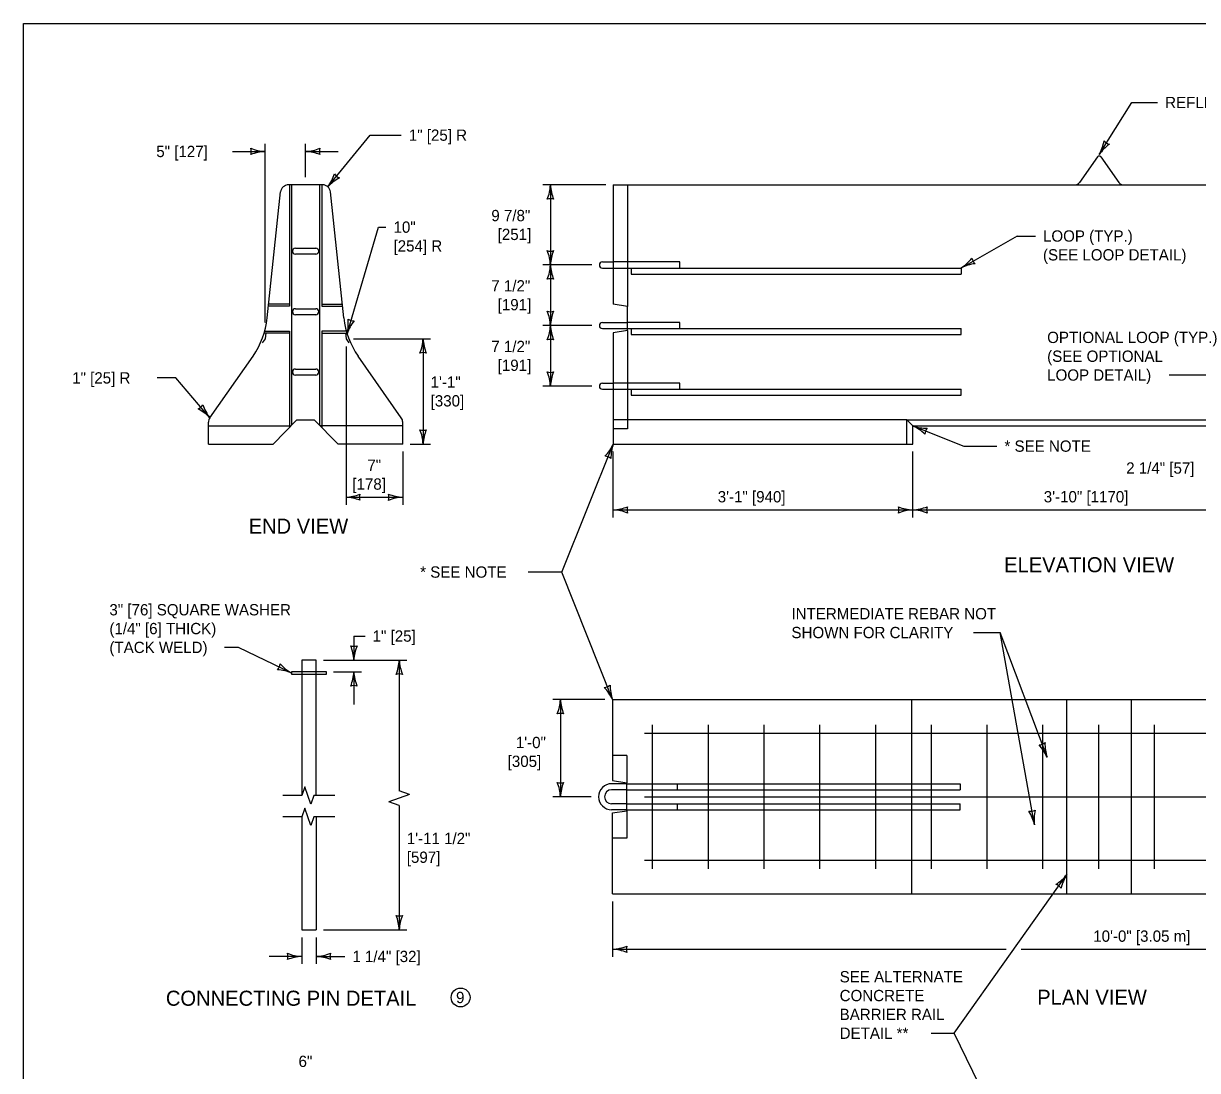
# Model space of a CAD drawing. Extents: x 49991.4 to 50021, y 49987.6 to 50011.4.
# Drawn here: x 49999.38 to 50005.62, y 49993.44 to 49999 of the extents above; entities that cross this region are included whole.
import ezdxf

# ---------------------------------------------------------------- set-up
doc = ezdxf.new("R2010")
doc.units = 0
for name, color, linetype in [('Level 1', 7, 'Continuous'), ('Level 2', 7, 'Continuous'), ('Level 3', 7, 'Continuous'), ('Level 4', 7, 'Continuous'), ('Level 6', 7, 'Continuous')]:
    doc.layers.add(name, color=color, linetype=linetype)

msp = doc.modelspace()

# ---------------------------------------------------------------- linework, layer by layer
at = {"layer": 'Level 1'}
for p, q in [((50000.6793, 49997.435), (50000.75, 49998.1041)), ((50000.9736, 49998.142), (50000.7921, 49998.142)), ((50000.7966, 49998.142), (50000.7966, 49997.4968)), ((50000.8081, 49998.142), (50000.8081, 49996.865)), ((50000.957, 49998.142), (50000.957, 49996.865)), ((50000.9685, 49998.142), (50000.9685, 49997.4968)), ((50001.0858, 49997.435), (50001.0151, 49998.1041)), ((50002.518, 49998.1414), (50007.607, 49998.1414)), ((50002.518, 49998.1414), (50002.518, 49997.5077)), ((50000.829, 49997.8057), (50000.9364, 49997.8057)), ((50000.9364, 49997.7735), (50000.829, 49997.7735)), ((50002.4602, 49997.7324), (50002.518, 49997.7323)), ((50002.4602, 49997.7002), (50002.518, 49997.7002)), ((50000.7966, 49997.4968), (50000.6858, 49997.4968)), ((50000.7966, 49997.5074), (50000.6869, 49997.5074)), ((50000.829, 49997.484), (50000.9364, 49997.484)), ((50000.9685, 49997.5074), (50001.0782, 49997.5074)), ((50000.9685, 49997.4968), (50001.0793, 49997.4968)), ((50002.5934, 49997.4961), (50002.518, 49997.5077)), ((50002.5934, 49997.3675), (50002.5934, 49997.4961)), ((50000.9364, 49997.4518), (50000.829, 49997.4518)), ((50002.4602, 49997.4107), (50002.5934, 49997.4106)), ((50000.7966, 49997.3541), (50000.6628, 49997.3541)), ((50000.6661, 49997.3654), (50000.7966, 49997.3654)), ((50000.7966, 49997.3654), (50000.7966, 49996.8533)), ((50000.9685, 49997.3654), (50000.9685, 49996.8533)), ((50001.099, 49997.3654), (50000.9685, 49997.3654)), ((50000.9685, 49997.3541), (50001.1023, 49997.3541)), ((50002.4602, 49997.3785), (50002.5934, 49997.3784)), ((50002.5934, 49997.3675), (50002.518, 49997.356)), ((50002.518, 49997.356), (50002.518, 49996.7646)), ((50000.3738, 49996.9047), (50000.6035, 49997.2325)), ((50001.3913, 49996.9047), (50001.1616, 49997.2325)), ((50000.829, 49997.1635), (50000.9364, 49997.1635)), ((50000.9364, 49997.1313), (50000.829, 49997.1313)), ((50002.4602, 49997.0884), (50002.518, 49997.0883)), ((50002.4602, 49997.0562), (50002.518, 49997.0562)), ((50000.3661, 49996.7651), (50000.3661, 49996.8804)), ((50000.7098, 49996.7651), (50000.8365, 49996.8938)), ((50000.8365, 49996.8938), (50000.9286, 49996.8938)), ((50001.0553, 49996.7651), (50000.9286, 49996.8938)), ((50001.399, 49996.7651), (50001.399, 49996.8804)), ((50004.0777, 49996.8932), (50006.1232, 49996.8932)), ((50004.0777, 49996.7646), (50004.0777, 49996.8932)), ((50004.0777, 49996.8932), (50004.1097, 49996.8611)), ((50004.1097, 49996.8611), (50006.0912, 49996.8611)), ((50004.1097, 49996.7646), (50004.1097, 49996.8611)), ((50000.3661, 49996.7651), (50000.7098, 49996.7651)), ((50001.399, 49996.7651), (50001.0553, 49996.7651)), ((50002.518, 49996.7646), (50004.1097, 49996.7646)), ((50000.9386, 49995.6169), (50000.8624, 49995.6169)), ((50000.8624, 49995.6169), (50000.8624, 49994.8978)), ((50000.9386, 49994.8977), (50000.9386, 49995.6169)), ((50000.8092, 49995.5561), (50000.992, 49995.5561)), ((50000.8092, 49995.5407), (50000.8092, 49995.5561)), ((50000.992, 49995.5407), (50000.8092, 49995.5407)), ((50000.992, 49995.5561), (50000.992, 49995.5407)), ((50002.5138, 49995.4076), (50007.6787, 49995.4076)), ((50002.5138, 49995.4076), (50002.5138, 49994.9771)), ((50004.9281, 49994.3747), (50004.9281, 49995.4076)), ((50005.2728, 49994.3747), (50005.2728, 49995.4076)), ((50002.6839, 49995.2287), (50007.5087, 49995.2287)), ((50002.7255, 49995.2739), (50002.7255, 49994.5084)), ((50003.0219, 49995.2739), (50003.0219, 49994.5084)), ((50003.3182, 49995.2739), (50003.3182, 49994.5084)), ((50003.6145, 49995.2739), (50003.6145, 49994.5084)), ((50003.9109, 49995.2739), (50003.9109, 49994.5084)), ((50004.2072, 49995.2739), (50004.2072, 49994.5084)), ((50004.5036, 49995.2739), (50004.5036, 49994.5084)), ((50004.7999, 49995.2739), (50004.7999, 49994.5084)), ((50005.0963, 49995.2739), (50005.0963, 49994.5084)), ((50005.3926, 49995.2739), (50005.3926, 49994.5084)), ((50002.5138, 49994.9771), (50002.5892, 49994.9656)), ((50002.5892, 49994.9604), (50002.5093, 49994.9604)), ((50002.5892, 49994.9284), (50002.5093, 49994.9284)), ((50002.5892, 49994.8168), (50002.5892, 49994.9656)), ((50002.5892, 49994.8537), (50002.5093, 49994.8537)), ((50002.6839, 49994.8911), (50007.5087, 49994.8911)), ((50002.5892, 49994.8217), (50002.5093, 49994.8217)), ((50002.5138, 49994.805), (50002.5892, 49994.8168)), ((50002.5138, 49994.3747), (50002.5138, 49994.805)), ((50000.8624, 49994.7844), (50000.8624, 49994.1841)), ((50000.9386, 49994.7843), (50000.9386, 49994.1841)), ((50002.6839, 49994.5537), (50007.5087, 49994.5537)), ((50002.5138, 49994.3747), (50007.6787, 49994.3747)), ((50000.8624, 49994.1841), (50000.9386, 49994.1841))]:
    msp.add_line(p, q, dxfattribs=at)
msp.add_lwpolyline([(49999.3835, 49998.9992), (50016.7501, 49998.9992), (50016.7501, 49987.7988), (49999.3835, 49987.7988)], close=True, dxfattribs=at)
for centre, radius, start, end in [((50000.7921, 49998.0996), 0.0423, 90, 173.97247), ((50000.973, 49998.0996), 0.0423, 6.02753, 90), ((50000.829, 49997.7896), 0.0161, 90, 270), ((50000.9364, 49997.7896), 0.0161, 270, 90), ((50002.4602, 49997.7163), 0.0161, 90, 270), ((50000.829, 49997.4679), 0.0161, 90, 270), ((50000.9364, 49997.4679), 0.0161, 270, 90), ((50000.2498, 49997.4803), 0.4318, 324.97771, 353.97247), ((50001.5153, 49997.4803), 0.4318, 186.02753, 215.02229), ((50002.4602, 49997.3946), 0.0161, 90, 270), ((50000.829, 49997.1474), 0.0161, 90, 270), ((50000.9364, 49997.1474), 0.0161, 270, 90), ((50002.4602, 49997.0723), 0.0161, 90, 270), ((50000.4084, 49996.8804), 0.0423, 144.97771, 180), ((50001.3567, 49996.8804), 0.0423, 0, 35.02229), ((50002.5093, 49994.8911), 0.0693, 90, 270), ((50002.5093, 49994.8911), 0.0374, 90, 270)]:
    msp.add_arc(centre, radius, start, end, dxfattribs=at)
at = {"layer": 'Level 2'}
msp.add_circle((50001.7068, 49993.8249), 0.05, dxfattribs=at)
at = {"layer": 'Level 3'}
for p, q in [((50005.1004, 49998.3024), (50005.2734, 49998.5794)), ((50005.2734, 49998.5794), (50005.411, 49998.5794)), ((50001.0015, 49998.1309), (50001.2252, 49998.406)), ((50001.2252, 49998.406), (50001.3915, 49998.406)), ((50000.6676, 49997.411), (50000.6676, 49998.3594)), ((50000.8828, 49998.182), (50000.8828, 49998.3594)), ((50000.4942, 49998.3194), (50000.6676, 49998.3194)), ((50000.8828, 49998.3194), (50001.0563, 49998.3194)), ((50005.0923, 49998.2909), (50004.9952, 49998.154)), ((50005.1086, 49998.2909), (50005.2057, 49998.154)), ((50002.478, 49998.1414), (50002.144, 49998.1414)), ((50002.184, 49998.1414), (50002.184, 49997.7163)), ((50001.1032, 49997.3512), (50001.2701, 49997.9175)), ((50001.2701, 49997.9175), (50001.3101, 49997.9175)), ((50004.6654, 49997.8702), (50004.3662, 49997.7002)), ((50004.6654, 49997.8702), (50004.7618, 49997.8702)), ((50002.4041, 49997.7163), (50002.144, 49997.7163)), ((50002.184, 49997.7163), (50002.184, 49997.3946)), ((50000.6708, 49997.3554), (50000.6675, 49997.3239)), ((50001.0943, 49997.3554), (50001.0976, 49997.3239)), ((50002.4041, 49997.3946), (50002.144, 49997.3946)), ((50002.184, 49997.3946), (50002.184, 49997.0723)), ((50000.6675, 49997.3239), (50000.6528, 49997.303)), ((50001.0976, 49997.3239), (50001.1123, 49997.303)), ((50001.0976, 49997.2839), (50001.0976, 49996.4423)), ((50001.1376, 49997.3239), (50001.5474, 49997.3239)), ((50001.5074, 49997.3239), (50001.5074, 49996.7651)), ((50000.1932, 49997.1164), (50000.0934, 49997.1164)), ((50000.3738, 49996.9047), (50000.1932, 49997.1164)), ((50005.7745, 49997.1316), (50005.4716, 49997.1316)), ((50002.4041, 49997.0723), (50002.144, 49997.0723)), ((50004.1097, 49996.8611), (50004.3802, 49996.7538)), ((50001.3992, 49996.7251), (50001.3992, 49996.4423)), ((50001.439, 49996.7651), (50001.5474, 49996.7651)), ((50002.2448, 49996.0849), (50002.518, 49996.7646)), ((50002.518, 49996.375), (50002.518, 49996.7246)), ((50004.1097, 49996.375), (50004.1097, 49996.7246)), ((50004.3802, 49996.7538), (50004.557, 49996.7538)), ((50001.0976, 49996.4823), (50001.3992, 49996.4823)), ((50002.518, 49996.415), (50004.1097, 49996.415)), ((50004.1097, 49996.415), (50006.0912, 49996.415)), ((50002.2448, 49996.0849), (50002.065, 49996.0849)), ((50002.5138, 49995.4076), (50002.2448, 49996.0849)), ((50001.1392, 49995.7449), (50001.1392, 49995.6171)), ((50001.1392, 49995.7449), (50001.1992, 49995.7449)), ((50004.4327, 49995.7636), (50004.5745, 49995.7636)), ((50004.8236, 49995.1014), (50004.5745, 49995.7636)), ((50004.7566, 49994.7424), (50004.5745, 49995.7636)), ((50000.5268, 49995.6847), (50000.4514, 49995.6847)), ((50000.8092, 49995.5483), (50000.5268, 49995.6847)), ((50000.9786, 49995.6171), (50001.4205, 49995.6171)), ((50001.3806, 49995.6171), (50001.3806, 49994.9226)), ((50001.032, 49995.5552), (50001.1792, 49995.5552)), ((50001.1392, 49995.5552), (50001.1392, 49995.3818)), ((50002.4738, 49995.4077), (50002.1971, 49995.4077)), ((50002.2371, 49995.4077), (50002.2371, 49994.8913)), ((50001.4352, 49994.9032), (50001.3806, 49994.9226)), ((50001.3806, 49994.8838), (50001.3256, 49994.8644)), ((50001.3806, 49994.845), (50001.3256, 49994.8644)), ((50001.4352, 49994.9032), (50001.3806, 49994.8838)), ((50002.4, 49994.8913), (50002.1971, 49994.8913)), ((50001.3806, 49994.845), (50001.3806, 49994.1843)), ((50004.3296, 49993.635), (50004.9281, 49994.4779)), ((50002.5138, 49994.3347), (50002.5138, 49994.0407)), ((50000.9786, 49994.1843), (50001.4205, 49994.1843)), ((50000.8624, 49994.1441), (50000.8624, 49994.0028)), ((50000.9386, 49994.1441), (50000.9386, 49994.0028)), ((50000.8624, 49994.0428), (50000.689, 49994.0428)), ((50000.9386, 49994.0428), (50001.0915, 49994.0428)), ((50002.5138, 49994.0807), (50004.6061, 49994.0807)), ((50004.6861, 49994.0807), (50007.6787, 49994.0807)), ((50004.2077, 49993.635), (50004.3296, 49993.635)), ((50005.0362, 49992.19), (50004.3296, 49993.635))]:
    msp.add_line(p, q, dxfattribs=at)
for centre, radius, start, end in [((50004.897, 49998.4159), 0.233, 330.85037, 350.10022), ((50005.284, 49998.177), 0.2223, 125.47907, 145.66258), ((50005.1683, 49998.4111), 0.0548, 220.16188, 255.88424), ((50000.5394, 49998.3194), 0.0548, 342.13882, 17.86118), ((50000.6791, 49998.5521), 0.233, 247.92284, 267.17269), ((50000.6768, 49998.0972), 0.2223, 92.36048, 112.54399), ((50000.8713, 49998.5521), 0.233, 272.82731, 292.07716), ((50000.8737, 49998.0972), 0.2223, 67.45601, 87.63952), ((50001.011, 49998.3194), 0.0548, 162.13882, 197.86118), ((50005.1004, 49998.2851), 0.01, 35.34894, 144.65106), ((50000.8137, 49998.2688), 0.233, 323.70951, 342.95936), ((50001.1681, 49997.9837), 0.2223, 118.33821, 138.52171), ((50001.0824, 49998.2304), 0.0548, 213.02101, 248.74337), ((50001.9619, 49998.1505), 0.2223, 337.45601, 357.63952), ((50002.4167, 49998.1529), 0.233, 182.82731, 202.07716), ((50004.9708, 49998.1714), 0.03, 270, 324.65106), ((50005.2301, 49998.1714), 0.03, 215.34894, 270), ((50002.184, 49998.0132), 0.0548, 72.13882, 107.86118), ((50002.184, 49997.8445), 0.0548, 252.13882, 287.86118), ((50001.9513, 49997.7048), 0.233, 2.82731, 22.07716), ((50002.4061, 49997.7072), 0.2223, 157.45601, 177.63952), ((50004.2485, 49997.8888), 0.2223, 301.96607, 322.14958), ((50004.4712, 49997.4922), 0.233, 97.52843, 116.77828), ((50004.4777, 49997.7635), 0.0548, 191.74441, 227.46677), ((50001.9619, 49997.7255), 0.2223, 337.45601, 357.63952), ((50002.4167, 49997.7278), 0.233, 182.82731, 202.07716), ((50002.184, 49997.5881), 0.0548, 72.13882, 107.86118), ((50002.184, 49997.5228), 0.0548, 252.13882, 287.86118), ((50001.9513, 49997.3831), 0.233, 2.82731, 22.07716), ((50002.4061, 49997.3854), 0.2223, 157.45601, 177.63952), ((50000.8767, 49997.406), 0.233, 346.40859, 5.65844), ((50001.3137, 49997.2796), 0.2223, 141.03729, 161.2208), ((50001.1394, 49997.4742), 0.0548, 235.7201, 271.44246), ((50001.9619, 49997.4037), 0.2223, 337.45601, 357.63952), ((50002.4167, 49997.4061), 0.233, 182.82731, 202.07716), ((50001.2852, 49997.3331), 0.2223, 337.45601, 357.63952), ((50001.7401, 49997.3354), 0.233, 182.82731, 202.07716), ((50002.184, 49997.2664), 0.0548, 72.13882, 107.86118), ((50001.5074, 49997.1957), 0.0548, 72.13882, 107.86118), ((50002.184, 49997.2005), 0.0548, 252.13882, 287.86118), ((50001.9513, 49997.0608), 0.233, 2.82731, 22.07716), ((50002.4061, 49997.0631), 0.2223, 157.45601, 177.63952), ((50000.2906, 49997.0022), 0.0548, 292.59303, 328.31539), ((50000.5487, 49997.0418), 0.2223, 197.91022, 218.09373), ((50000.2041, 49996.7449), 0.233, 43.28152, 62.53137), ((50004.0193, 49996.6579), 0.2223, 45.83501, 66.01852), ((50004.1848, 49997.0816), 0.233, 251.20631, 270.45616), ((50004.2289, 49996.8138), 0.0548, 140.51782, 176.24018), ((50001.5074, 49996.8933), 0.0548, 252.13882, 287.86118), ((50001.2746, 49996.7536), 0.233, 2.82731, 22.07716), ((50001.7295, 49996.7559), 0.2223, 157.45601, 177.63952), ((50002.3153, 49996.8559), 0.2223, 315.56008, 335.74359), ((50002.7382, 49996.6885), 0.233, 160.93138, 180.18123), ((50002.4702, 49996.6456), 0.0548, 50.24289, 85.96525), ((50001.0866, 49996.7051), 0.2231, 272.82731, 292.07716), ((50001.0888, 49996.2697), 0.2129, 67.45601, 87.63952), ((50001.2204, 49996.4823), 0.0524, 162.13882, 197.86118), ((50001.4084, 49996.7045), 0.2223, 247.45601, 267.63952), ((50001.271, 49996.4823), 0.0548, 342.13882, 17.86118), ((50001.4107, 49996.2496), 0.233, 92.82731, 112.07716), ((50002.5065, 49996.6477), 0.233, 272.82731, 292.07716), ((50002.5088, 49996.1929), 0.2223, 67.45601, 87.63952), ((50002.6462, 49996.415), 0.0548, 162.13882, 197.86118), ((50004.1189, 49996.6371), 0.2223, 247.45601, 267.63952), ((50003.9815, 49996.415), 0.0548, 342.13882, 17.86118), ((50004.1212, 49996.1823), 0.233, 92.82731, 112.07716), ((50004.0982, 49996.6477), 0.233, 272.82731, 292.07716), ((50004.1005, 49996.1929), 0.2223, 67.45601, 87.63952), ((50004.2379, 49996.415), 0.0548, 162.13882, 197.86118), ((50001.1392, 49995.7453), 0.0548, 252.13882, 287.86118), ((50000.9065, 49995.6056), 0.233, 2.82731, 22.07716), ((50001.3614, 49995.608), 0.2223, 157.45601, 177.63952), ((50000.6937, 49995.604), 0.0548, 316.3746, 352.09696), ((50000.914, 49995.7444), 0.2223, 221.69179, 241.8753), ((50001.1584, 49995.6263), 0.2223, 337.45601, 357.63952), ((50001.6133, 49995.6286), 0.233, 182.82731, 202.07716), ((50000.7184, 49995.3337), 0.233, 67.06309, 86.31294), ((50000.9171, 49995.5643), 0.2223, 337.45601, 357.63952), ((50001.3719, 49995.5667), 0.233, 182.82731, 202.07716), ((50001.3806, 49995.4889), 0.0548, 72.13882, 107.86118), ((50001.1392, 49995.427), 0.0548, 72.13882, 107.86118), ((50002.4665, 49995.5268), 0.0548, 273.80036, 309.52272), ((50002.3018, 49995.311), 0.233, 24.48885, 43.7387), ((50002.7236, 49995.4811), 0.2223, 179.11755, 199.30106), ((50002.015, 49995.4168), 0.2223, 337.45601, 357.63952), ((50002.4698, 49995.4192), 0.233, 182.82731, 202.07716), ((50002.2371, 49995.2795), 0.0548, 72.13882, 107.86118), ((50004.7784, 49995.2214), 0.0548, 272.74951, 308.47187), ((50004.6098, 49995.0087), 0.233, 23.438, 42.68785), ((50005.0347, 49995.171), 0.2223, 178.0667, 198.25021), ((50002.2371, 49995.0195), 0.0548, 252.13882, 287.86118), ((50002.0044, 49994.8798), 0.233, 2.82731, 22.07716), ((50002.4592, 49994.8822), 0.2223, 157.45601, 177.63952), ((50004.7341, 49994.8686), 0.0548, 262.24768, 297.97004), ((50004.5295, 49994.6902), 0.233, 12.93618, 32.18603), ((50004.9769, 49994.7723), 0.2223, 167.56488, 187.74838), ((50004.7523, 49994.6139), 0.2223, 302.07943, 322.26294), ((50005.1245, 49994.3525), 0.233, 147.45073, 166.70058), ((50004.8539, 49994.3733), 0.0548, 36.76224, 72.4846), ((50001.3806, 49994.3125), 0.0548, 252.13882, 287.86118), ((50001.1479, 49994.1728), 0.233, 2.82731, 22.07716), ((50001.6027, 49994.1752), 0.2223, 157.45601, 177.63952), ((50000.8715, 49994.265), 0.2223, 247.45601, 267.63952), ((50000.7342, 49994.0428), 0.0548, 342.13882, 17.86118), ((50000.8739, 49993.8101), 0.233, 92.82731, 112.07716), ((50000.9271, 49994.2756), 0.233, 272.82731, 292.07716), ((50000.9294, 49993.8207), 0.2223, 67.45601, 87.63952), ((50001.0668, 49994.0428), 0.0548, 162.13882, 197.86118), ((50002.5023, 49994.3134), 0.233, 272.82731, 292.07716), ((50002.5047, 49993.8585), 0.2223, 67.45601, 87.63952), ((50002.642, 49994.0807), 0.0548, 162.13882, 197.86118)]:
    msp.add_arc(centre, radius, start, end, dxfattribs=at)
at = {"layer": 'Level 4'}
for p, q in [((50002.5934, 49998.1414), (50002.5934, 49997.4961)), ((50002.871, 49997.7323), (50002.518, 49997.7323)), ((50002.871, 49997.7002), (50002.871, 49997.7323)), ((50002.518, 49997.7002), (50004.3662, 49997.7002)), ((50002.6136, 49997.7002), (50002.6136, 49997.6681)), ((50002.6136, 49997.6681), (50004.3662, 49997.6681)), ((50004.3662, 49997.7002), (50004.3662, 49997.6681)), ((50002.871, 49997.4106), (50002.5934, 49997.4106)), ((50002.871, 49997.3784), (50002.871, 49997.4106)), ((50002.5934, 49997.3784), (50004.3662, 49997.3784)), ((50002.5934, 49997.3675), (50002.5934, 49996.845)), ((50002.6136, 49997.3784), (50002.6136, 49997.3461)), ((50002.6136, 49997.3461), (50004.3662, 49997.3461)), ((50004.3662, 49997.3461), (50004.3662, 49997.3784)), ((50002.871, 49997.0883), (50002.518, 49997.0883)), ((50002.518, 49997.0562), (50004.3662, 49997.0562)), ((50002.6136, 49997.0562), (50002.6136, 49997.0238)), ((50002.871, 49997.0562), (50002.871, 49997.0883)), ((50004.3662, 49997.0238), (50004.3662, 49997.0562)), ((50002.6136, 49997.0238), (50004.3662, 49997.0238)), ((50000.3661, 49996.8616), (50000.8048, 49996.8616)), ((50001.399, 49996.8616), (50000.9603, 49996.8616)), ((50004.0777, 49996.8932), (50002.518, 49996.8932)), ((50002.5934, 49996.845), (50002.518, 49996.845)), ((50004.1055, 49994.3747), (50004.1055, 49995.4076)), ((50002.5892, 49995.1103), (50002.5138, 49995.1103)), ((50002.5892, 49995.1103), (50002.5892, 49994.9656)), ((50002.5892, 49994.9604), (50004.362, 49994.9604)), ((50002.5892, 49994.9284), (50004.362, 49994.9284)), ((50002.86, 49994.9284), (50002.86, 49994.9604)), ((50004.362, 49994.9604), (50004.362, 49994.9284)), ((50002.5892, 49994.8537), (50004.362, 49994.8537)), ((50002.86, 49994.8217), (50002.86, 49994.8537)), ((50004.362, 49994.8217), (50004.362, 49994.8537)), ((50002.5892, 49994.8217), (50004.362, 49994.8217)), ((50002.5892, 49994.8168), (50002.5892, 49994.6718)), ((50002.5892, 49994.6718), (50002.5138, 49994.6718))]:
    msp.add_line(p, q, dxfattribs=at)
at = {"layer": 'Level 6'}
for p, q in [((50000.8786, 49994.9435), (50000.8624, 49994.8977)), ((50000.8948, 49994.8977), (50000.8786, 49994.9435)), ((50000.8624, 49994.8977), (50000.7624, 49994.8979)), ((50000.911, 49994.8521), (50000.8948, 49994.8977)), ((50000.9272, 49994.8977), (50000.911, 49994.8521)), ((50001.0386, 49994.8975), (50000.9272, 49994.8977)), ((50000.8786, 49994.8301), (50000.8624, 49994.7843)), ((50000.8948, 49994.7843), (50000.8786, 49994.8301)), ((50000.8624, 49994.7843), (50000.7624, 49994.7845)), ((50000.911, 49994.7387), (50000.8948, 49994.7843)), ((50000.9272, 49994.7843), (50000.911, 49994.7387)), ((50001.0386, 49994.7841), (50000.9272, 49994.7843))]:
    msp.add_line(p, q, dxfattribs=at)

# ---------------------------------------------------------------- texts
at = {"layer": 'Level 2'}
for s, height, p in [('REFLECTOR  6', 0.06, (50005.451, 49998.5495)), ('1" [25] R', 0.06, (50001.4315, 49998.376)), ('5" [127]', 0.06, (50000.0892, 49998.2894)), ('9 7/8"', 0.06, (50001.8699, 49997.9488)), ('10" ', 0.06, (50001.3501, 49997.8875)), ('[251]', 0.06, (50001.9036, 49997.8488)), ('[254] R', 0.06, (50001.3501, 49997.7875)), ('LOOP (TYP.)', 0.06, (50004.8018, 49997.8402)), ('(SEE LOOP DETAIL)', 0.06, (50004.8018, 49997.7402)), ('7 1/2"', 0.06, (50001.8699, 49997.5755)), ('[191]', 0.06, (50001.9036, 49997.4755)), ('OPTIONAL LOOP (TYP.)', 0.06, (50004.824, 49997.3016)), ('7 1/2"', 0.06, (50001.8699, 49997.2534)), ('(SEE OPTIONAL', 0.06, (50004.824, 49997.2016)), ('[191]', 0.06, (50001.9036, 49997.1534)), ('LOOP DETAIL)', 0.06, (50004.824, 49997.1016)), ('1" [25] R', 0.06, (49999.6423, 49997.0864)), ('1\'-1"', 0.06, (50001.5474, 49997.0645)), ('[330]', 0.06, (50001.5474, 49996.9645)), ('* SEE NOTE', 0.06, (50004.597, 49996.7239)), ('7"', 0.06, (50001.2111, 49996.6223)), ('2 1/4" [57]', 0.06, (50005.244, 49996.6075)), ('[178]', 0.06, (50001.1313, 49996.5223)), ('3\'-1" [940]', 0.06, (50003.0732, 49996.455)), ('3\'-10" [1170]', 0.06, (50004.806, 49996.455)), ('END VIEW', 0.08, (50000.5802, 49996.2888)), ('ELEVATION VIEW', 0.08, (50004.5951, 49996.0839)), ('* SEE NOTE', 0.06, (50001.4917, 49996.0549)), ('3" [76] SQUARE WASHER', 0.06, (49999.8402, 49995.8547)), ('INTERMEDIATE REBAR NOT ', 0.06, (50003.465, 49995.8336)), ('(1/4" [6] THICK)', 0.06, (49999.8402, 49995.7547)), ('SHOWN FOR CLARITY', 0.06, (50003.465, 49995.7336)), ('1" [25]', 0.06, (50001.2392, 49995.7149)), ('(TACK WELD)', 0.06, (49999.8402, 49995.6547)), ('1\'-0"', 0.06, (50002.0002, 49995.1495)), ('[305]', 0.06, (50001.9567, 49995.0495)), ('1\'-11 1/2"', 0.06, (50001.4206, 49994.6398)), ('[597]', 0.06, (50001.4206, 49994.5398)), ('10\'-0" [3.05 m]', 0.06, (50005.069, 49994.1207)), ('1 1/4" [32]', 0.06, (50001.1315, 49994.0128)), ('SEE ALTERNATE ', 0.06, (50003.7212, 49993.905)), ('CONNECTING PIN DETAIL', 0.08, (50000.1403, 49993.7808)), ('9', 0.06, (50001.6823, 49993.7949)), ('CONCRETE ', 0.06, (50003.7212, 49993.805)), ('PLAN VIEW', 0.08, (50004.771, 49993.7858)), ('BARRIER RAIL', 0.06, (50003.7212, 49993.705)), ('DETAIL **', 0.06, (50003.7212, 49993.605)), ('6"', 0.06, (50000.8454, 49993.4556))]:
    msp.add_text(s, height=height, dxfattribs=at).set_placement(p)

doc.saveas('drawing.dxf')
